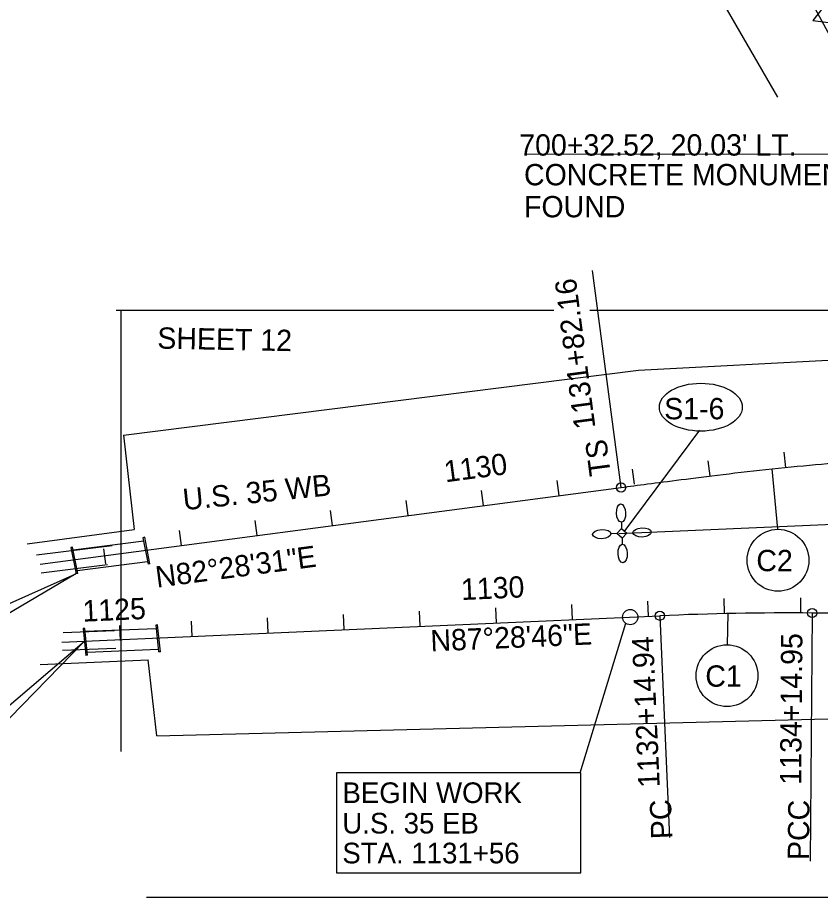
# Model space of a CAD drawing. Extents: x 310 to 1844719, y 48 to 494239.
# Drawn here: x 1835985 to 1837039, y 491431 to 492586 of the extents above; entities that cross this region are included whole.
import ezdxf

# ---------------------------------------------------------------- set-up
doc = ezdxf.new("R2010")
doc.units = 0
for name, color, linetype in [('6ft clearance', 7, 'Continuous'), ('Default', 7, 'Continuous'), ('Guardrail', 7, 'Continuous'), ('LT_P_Control_Center', 7, 'Continuous'), ('LT_P_PullBox', 7, 'Continuous'), ('PV_X_Curb', 7, 'Continuous'), ('PV_X_EOP', 7, 'Continuous'), ('SC_Scratch2', 7, 'Continuous'), ('Shoulder lines', 7, 'Continuous'), ('Traffic Sign', 7, 'Continuous'), ('VG_X_Tree_Line_Lt', 7, 'Continuous'), ('VG_X_Tree_Line_Rt', 7, 'Continuous')]:
    doc.layers.add(name, color=color, linetype=linetype)

msp = doc.modelspace()

# ---------------------------------------------------------------- linework, layer by layer
at = {"layer": '6ft clearance'}
msp.add_line((1836777.7, 491969.3), (1836777.7, 491969.3), dxfattribs=at)
at = {"layer": 'Default'}
for p, q in [((1836983.7, 492481.4), (1836598, 493149.1)), ((1836689.3, 492201.8), (1836114.6, 492201.8)), ((1836120.5, 492200.6), (1836120.5, 491622.6)), ((1836753.7, 492201.8), (1836736.8, 492201.8)), ((1837189.9, 492201.8), (1836753.1, 492201.8)), ((1836014.7, 491868.5), (1836777.7, 491969.3)), ((1836152.1, 491903.9), (1836149.8, 491903.4)), ((1836149.8, 491903.4), (1836156.6, 491868.7)), ((1836158.9, 491869.1), (1836152.1, 491903.9)), ((1836057.4, 491891), (1836055.1, 491890.5)), ((1836055.1, 491890.5), (1836061.9, 491855.8)), ((1836064.2, 491856.3), (1836057.4, 491891)), ((1836058.2, 491887.3), (1836150.7, 491899.1)), ((1836155.9, 491871.8), (1836063.5, 491859.7)), ((1836158.9, 491869.1), (1836156.6, 491868.7)), ((1836064.2, 491856.3), (1836061.9, 491855.8)), ((1836168.8, 491788.8), (1836166.5, 491788.6)), ((1836166.5, 491788.6), (1836170.2, 491753.4)), ((1836172.6, 491753.6), (1836168.8, 491788.8)), ((1836073.4, 491784.3), (1836071.1, 491784)), ((1836071.1, 491784), (1836074.8, 491748.8)), ((1836077.1, 491749.1), (1836073.4, 491784.3)), ((1836073.8, 491780.6), (1836167, 491784.2)), ((1836169.8, 491756.6), (1836076.7, 491752.5)), ((1836172.6, 491753.6), (1836170.2, 491753.4)), ((1836077.1, 491749.1), (1836074.8, 491748.8)), ((1837590, 491431.3), (1836154.6, 491431.3))]:
    msp.add_line(p, q, dxfattribs=at)
msp.add_lwpolyline([(1836043.4, 491766.3), (1836728.7, 491796.5), (1836828.6, 491800.9)], dxfattribs=at)
for centre, radius, start, end in [((1838906.9, 493374.4), 1909.9, 189.0038, 224.841), ((1836996.6, 487984.9), 3819.7, 89.5204, 92.5205), ((1837004.6, 488939.8), 2864.8, 60.6408, 89.5206)]:
    msp.add_arc(centre, radius, start, end, dxfattribs=at)
msp.add_open_spline([(1836777.7, 491969.3), (1836788.7, 491970.8), (1836810.7, 491973.7), (1836854.8, 491979.4), (1836909.9, 491986.4), (1836976.1, 491994), (1837042.5, 492000.4), (1837097.9, 492004.4), (1837142.3, 492006.7), (1837164.5, 492007.5), (1837175.6, 492007.8)], degree=3, dxfattribs=at)
at = {"layer": 'LT_P_Control_Center'}
for p, q in [((1836778.1, 491923.6), (1836778.4, 491915.5)), ((1836772.3, 491908.9), (1836764.2, 491908.6)), ((1836778.9, 491902.8), (1836779.3, 491894.7)), ((1836785, 491909.4), (1836793.1, 491909.8))]:
    msp.add_line(p, q, dxfattribs=at)
msp.add_lwpolyline([(1836778.9, 491902.8), (1836772.3, 491908.9), (1836778.4, 491915.5), (1836785, 491909.4)], close=True, dxfattribs=at)
for centre, major_axis in [((1836777.6, 491935.7), (-0.5, 12)), ((1836752.2, 491908.1), (-12, -0.5)), ((1836805.2, 491910.3), (12, 0.5)), ((1836779.7, 491882.7), (-0.5, 12.1))]:
    msp.add_ellipse(centre, major_axis=major_axis, ratio=0.5, dxfattribs=at)
at = {"layer": 'LT_P_PullBox'}
msp.add_line((1836774.6, 491909.1), (1837212.3, 491927.7), dxfattribs=at)
at = {"layer": 'PV_X_Curb'}
for p, q in [((1837276.3, 492148), (1837002.7, 492653)), ((1836800.5, 492123.5), (1837439.6, 492156.5)), ((1836124, 492038.1), (1836800.5, 492123.5)), ((1836124, 492038.1), (1836138, 491914)), ((1835997.5, 491895.5), (1836138, 491914)), ((1836014.7, 491736.9), (1836156.6, 491743.1)), ((1836167.8, 491643.5), (1836156.6, 491743.1)), ((1836167.8, 491643.5), (1837204.2, 491669.3))]:
    msp.add_line(p, q, dxfattribs=at)
at = {"layer": 'PV_X_EOP'}
for p, q in [((1836993.9, 491995.6), (1836991.9, 492015.5)), ((1836894.5, 491984.5), (1836892.1, 492004.3)), ((1836795.1, 491973.7), (1836792.5, 491993.5)), ((1836696.2, 491958.6), (1836693.6, 491978.4)), ((1836597.1, 491945.5), (1836594.5, 491965.3)), ((1836497.9, 491932.4), (1836495.3, 491952.2)), ((1836398.8, 491919.3), (1836396.2, 491939.1)), ((1836299.7, 491906.2), (1836297, 491926)), ((1836200.5, 491893.1), (1836197.9, 491912.9)), ((1836101, 491869), (1836098.3, 491888.9)), ((1836913.6, 491803.7), (1836913.2, 491823.7)), ((1837013.6, 491804.6), (1837013.7, 491824.6)), ((1836613.9, 491791.5), (1836613, 491811.4)), ((1836713.8, 491795.9), (1836712.9, 491815.8)), ((1836813.7, 491800.3), (1836812.8, 491820.2)), ((1836314.2, 491778.3), (1836313.3, 491798.2)), ((1836414.1, 491782.7), (1836413.2, 491802.6)), ((1836514, 491787.1), (1836513.1, 491807)), ((1836120.3, 491768.3), (1836119.5, 491788.3)), ((1836214.3, 491773.9), (1836213.4, 491793.8))]:
    msp.add_line(p, q, dxfattribs=at)
at = {"layer": 'SC_Scratch2'}
msp.add_lwpolyline([(1837108.7, 492572.1), (1837078.7, 492644.9), (1837029.6, 492582.1)], close=True, dxfattribs=at)
at = {"layer": 'Shoulder lines'}
for p, q in [((1837114.2, 492406.3), (1836652.1, 492406.6)), ((1836880.6, 492044.6), (1836781.2, 491911.3)), ((1836723.8, 491594.9), (1836784, 491791))]:
    msp.add_line(p, q, dxfattribs=at)
msp.add_lwpolyline([(1836724.6, 491594.9), (1836404, 491594.9), (1836404, 491463.5), (1836724.6, 491463.5)], close=True, dxfattribs=at)
msp.add_circle((1836789.7, 491799.2), 10, dxfattribs=at)
msp.add_ellipse((1836882.4, 492074.7), major_axis=(-54.4, 0), ratio=0.57803, dxfattribs=at)
at = {"layer": 'Traffic Sign'}
for p, q in [((1836777.7, 491969.3), (1836740, 492254.3)), ((1836983.7, 491914.5), (1836976.2, 491993.8)), ((1836828.6, 491800.9), (1836841.4, 491509.9)), ((1836917.6, 491762.9), (1836918.2, 491803.8)), ((1837028.6, 491804.5), (1837025.8, 491478.7))]:
    msp.add_line(p, q, dxfattribs=at)
for centre, radius in [((1836777.7, 491969.3), 6), ((1836983.7, 491873.8), 40.6), ((1837028.6, 491804.5), 6), ((1836828.6, 491800.9), 6), ((1836916.8, 491722.3), 40.6)]:
    msp.add_circle(centre, radius, dxfattribs=at)
at = {"layer": 'VG_X_Tree_Line_Lt'}
for p, q in [((1836061.5, 491856), (1835941.1, 491784.9)), ((1835941.1, 491802.3), (1836061.5, 491856)), ((1836072.8, 491767.7), (1835955.7, 491647.5)), ((1835955.9, 491667.7), (1836072.8, 491767.7))]:
    msp.add_line(p, q, dxfattribs=at)
at = {"layer": 'VG_X_Tree_Line_Rt'}
for p, q in [((1836009.9, 491880.7), (1836109.2, 491893.1)), ((1836016.2, 491857.3), (1836103.1, 491868.1)), ((1836045.1, 491778.9), (1836112.3, 491781.7)), ((1836114.3, 491758), (1836043.9, 491755.2))]:
    msp.add_line(p, q, dxfattribs=at)

# ---------------------------------------------------------------- texts
at = {"layer": 'Guardrail'}
msp.add_text('N87°28\'46"E', height=28, rotation=2.5204, dxfattribs=at).set_placement((1836527.9, 491754))
at = {"layer": 'PV_X_EOP'}
for s, rotation, p in [("700+32.52, 20.03' LT.", 0.0079, (1836643.9, 492404.9)), ('CONCRETE MONUMENT ', 0.0079, (1836650.2, 492365.9)), ('FOUND', 0.0079, (1836650.2, 492323.9)), ('1130', 2.5204, (1836568, 491821.5)), ('1125', 2.5204, (1836070.9, 491793.1))]:
    msp.add_text(s, height=28, rotation=rotation, dxfattribs=at).set_placement(p)
at = {"layer": 'Shoulder lines'}
msp.add_text('SHEET 12', height=28, rotation=358.8848, dxfattribs=at).set_placement((1836168.4, 492151.6))
for s, height, p in [('S1-6', 28, (1836834.3, 492058.8)), ('BEGIN WORK', 27.1, (1836411.8, 491555.1)), ('U.S. 35 EB', 27.1, (1836411.6, 491515.1)), ('STA. 1131+56', 27.104, (1836411.6, 491475.9))]:
    msp.add_text(s, height=height, dxfattribs=at).set_placement(p)
at = {"layer": 'Traffic Sign'}
for s, rotation, p in [('1131+82.16', 97.5249, (1836744.1, 492047.9)), ('TS', 97.5249, (1836764.3, 491986.4)), ('1130', 7.5249, (1836547, 491976)), ('U.S. 35 WB', 5.7933, (1836203.5, 491939.4)), ('N82°28\'31"E', 7.5249, (1836168.1, 491837.7)), ('1134+14.95', 89.5206, (1837014.2, 491579.1)), ('1132+14.94', 92.5205, (1836828.5, 491575.9)), ('PC', 92.5205, (1836845.3, 491508.4)), ('PCC', 89.5206, (1837024.5, 491480.2))]:
    msp.add_text(s, height=28, rotation=rotation, dxfattribs=at).set_placement(p)
for s, p in [('C2', (1836955.3, 491859.4)), ('C1', (1836888.3, 491707.8))]:
    msp.add_text(s, height=28, dxfattribs=at).set_placement(p)

doc.saveas('drawing.dxf')
